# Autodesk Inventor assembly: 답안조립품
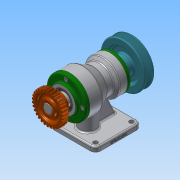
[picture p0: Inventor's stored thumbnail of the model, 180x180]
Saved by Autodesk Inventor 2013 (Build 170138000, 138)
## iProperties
Created: 2019-01
Part Number: 답안조립품
Document SubType Name: Assembly
Designer: Administrator
Author: Administrator
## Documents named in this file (15)
- C:\Users\Administrator\Desktop\490107V1041\답안조립품.iam
- C:\Users\Administrator\Desktop\490107V1041\본체.ipt
- C:\Users\Administrator\Desktop\490107V1041\490107V1041\V-벨트풀리.ipt
- C:\Users\Administrator\Desktop\490107V1041\490107V1041\뒤커버.ipt
- C:\Users\Administrator\Desktop\490107V1041\490107V1041\멈춤나사 M3.ipt
- C:\Users\Administrator\Desktop\490107V1041\490107V1041\베어링 6203.ipt
- C:\Users\Administrator\Desktop\490107V1041\490107V1041\베어링 6205.ipt
- C:\Users\Administrator\Desktop\490107V1041\490107V1041\볼트 M4.ipt
- C:\Users\Administrator\Desktop\490107V1041\490107V1041\스퍼기어.ipt
- C:\Users\Administrator\Desktop\490107V1041\490107V1041\앞커버.ipt
- C:\Users\Administrator\Desktop\490107V1041\490107V1041\오일 실 17 30 8.ipt
- C:\Users\Administrator\Desktop\490107V1041\490107V1041\오일 실 25 38 8.ipt
- C:\Users\Administrator\Desktop\490107V1041\490107V1041\축.ipt
- C:\Users\Administrator\Desktop\490107V1041\490107V1041\키 5 x 5 x 20.ipt
- C:\Users\Administrator\Desktop\490107V1041\490107V1041\키 6 x 6 x 18.ipt
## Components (1 placed, 1 different names)
1. V-벨트풀리:1 — 플러쉬:1
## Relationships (1: Flush 1)
- 플러쉬:1 [Flush]: V-벨트풀리:1
